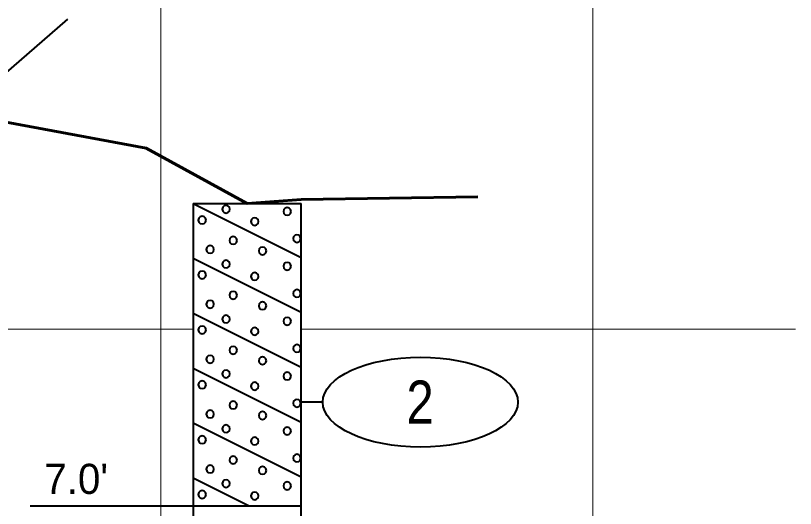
# Model space of a CAD drawing. Extents: x -76 to 974, y -1080 to -735.
# Drawn here: x 190.03 to 208.08, y -936.24 to -924.83 of the extents above; entities that cross this region are included whole.
import ezdxf
from ezdxf.enums import TextEntityAlignment as Align

# ---------------------------------------------------------------- set-up
doc = ezdxf.new("R2010")
doc.units = 0
doc.header["$LTSCALE"] = 0.36
doc.linetypes.add('LONG_DASHED', pattern=[7.5, 6, -1.5])
for name, color, linetype, lineweight in [('27', 7, 'Continuous', 40), ('28', 7, 'LONG_DASHED', 60), ('7', 7, 'Continuous', 13)]:
    doc.layers.add(name, color=color, linetype=linetype, lineweight=lineweight)

msp = doc.modelspace()

# ---------------------------------------------------------------- linework, layer by layer
at = {"layer": '27'}
for p, q in [((188.7243, -927.0998), (191.2447, -924.9175)), ((194.1412, -929.1789), (196.6412, -930.4289)), ((194.1412, -929.1789), (194.1412, -936.1789)), ((194.1412, -929.1789), (196.6412, -929.1789)), ((196.6412, -936.1789), (196.6412, -929.1789)), ((194.1412, -930.4489), (196.6412, -931.6989)), ((194.1412, -931.7189), (196.6412, -932.9689)), ((194.1412, -932.9889), (196.6412, -934.2389)), ((197.1412, -933.7789), (196.6412, -933.7789)), ((194.1412, -934.2589), (196.6412, -935.5089)), ((194.1412, -935.5289), (195.4412, -936.1789)), ((190.3737, -936.1789), (194.1411, -936.1789)), ((194.1412, -936.1789), (196.6412, -936.1789)), ((194.1412, -936.1789), (194.1412, -946.1789)), ((196.6412, -946.1789), (196.6412, -936.1789))]:
    msp.add_line(p, q, dxfattribs=at)
for points in [[(194.9918, -929.3152), (194.9799, -929.2708), (194.9474, -929.2383), (194.9029, -929.2263), (194.8585, -929.2383), (194.826, -929.2708), (194.814, -929.3152), (194.826, -929.3597), (194.8585, -929.3922), (194.9029, -929.4041), (194.9474, -929.3922), (194.9799, -929.3597)], [(196.4067, -929.3662), (196.3948, -929.3217), (196.3622, -929.2892), (196.3178, -929.2773), (196.2733, -929.2892), (196.2408, -929.3217), (196.2289, -929.3662), (196.2408, -929.4106), (196.2733, -929.4432), (196.3178, -929.4551), (196.3622, -929.4432), (196.3948, -929.4106)], [(194.4388, -929.567), (194.4268, -929.5226), (194.3943, -929.49), (194.3499, -929.4781), (194.3054, -929.49), (194.2729, -929.5226), (194.261, -929.567), (194.2729, -929.6115), (194.3054, -929.644), (194.3499, -929.6559), (194.3943, -929.644), (194.4268, -929.6115)], [(195.6541, -929.6001), (195.6422, -929.5556), (195.6096, -929.5231), (195.5652, -929.5112), (195.5207, -929.5231), (195.4882, -929.5556), (195.4763, -929.6001), (195.4882, -929.6445), (195.5207, -929.6771), (195.5652, -929.689), (195.6096, -929.6771), (195.6422, -929.6445)], [(196.633, -929.9942), (196.6211, -929.9497), (196.5885, -929.9172), (196.5441, -929.9053), (196.4996, -929.9172), (196.4671, -929.9497), (196.4552, -929.9942), (196.4671, -930.0386), (196.4996, -930.0712), (196.5441, -930.0831), (196.5885, -930.0712), (196.6211, -930.0386)], [(195.1583, -930.0374), (195.1464, -929.993), (195.1138, -929.9604), (195.0694, -929.9485), (195.0249, -929.9604), (194.9924, -929.993), (194.9805, -930.0374), (194.9924, -930.0819), (195.0249, -930.1144), (195.0694, -930.1263), (195.1138, -930.1144), (195.1464, -930.0819)], [(194.6231, -930.2459), (194.6112, -930.2014), (194.5786, -930.1689), (194.5342, -930.157), (194.4897, -930.1689), (194.4572, -930.2014), (194.4453, -930.2459), (194.4572, -930.2903), (194.4897, -930.3229), (194.5342, -930.3348), (194.5786, -930.3229), (194.6112, -930.2903)], [(195.8359, -930.2789), (195.824, -930.2345), (195.7914, -930.202), (195.747, -930.19), (195.7025, -930.202), (195.67, -930.2345), (195.6581, -930.2789), (195.67, -930.3234), (195.7025, -930.3559), (195.747, -930.3678), (195.7914, -930.3559), (195.824, -930.3234)], [(194.9918, -930.584), (194.9799, -930.5396), (194.9473, -930.5071), (194.9029, -930.4951), (194.8584, -930.5071), (194.8259, -930.5396), (194.814, -930.584), (194.8259, -930.6285), (194.8584, -930.661), (194.9029, -930.6729), (194.9473, -930.661), (194.9799, -930.6285)], [(196.4067, -930.6349), (196.3948, -930.5904), (196.3622, -930.5579), (196.3178, -930.546), (196.2733, -930.5579), (196.2408, -930.5904), (196.2289, -930.6349), (196.2408, -930.6793), (196.2733, -930.7119), (196.3178, -930.7238), (196.3622, -930.7119), (196.3948, -930.6793)], [(194.4388, -930.8358), (194.4268, -930.7913), (194.3943, -930.7588), (194.3499, -930.7469), (194.3054, -930.7588), (194.2729, -930.7913), (194.261, -930.8358), (194.2729, -930.8802), (194.3054, -930.9127), (194.3499, -930.9247), (194.3943, -930.9127), (194.4268, -930.8802)], [(195.6541, -930.8688), (195.6422, -930.8244), (195.6096, -930.7918), (195.5652, -930.7799), (195.5207, -930.7918), (195.4882, -930.8244), (195.4763, -930.8688), (195.4882, -930.9133), (195.5207, -930.9458), (195.5652, -930.9577), (195.6096, -930.9458), (195.6422, -930.9133)], [(196.633, -931.2629), (196.6211, -931.2185), (196.5885, -931.1859), (196.5441, -931.174), (196.4996, -931.1859), (196.4671, -931.2185), (196.4552, -931.2629), (196.4671, -931.3074), (196.4996, -931.3399), (196.5441, -931.3518), (196.5885, -931.3399), (196.6211, -931.3074)], [(195.1583, -931.3061), (195.1464, -931.2617), (195.1138, -931.2291), (195.0694, -931.2172), (195.0249, -931.2291), (194.9924, -931.2617), (194.9805, -931.3061), (194.9924, -931.3506), (195.0249, -931.3831), (195.0694, -931.395), (195.1138, -931.3831), (195.1464, -931.3506)], [(194.6231, -931.5146), (194.6112, -931.4702), (194.5786, -931.4376), (194.5342, -931.4257), (194.4897, -931.4376), (194.4572, -931.4702), (194.4453, -931.5146), (194.4572, -931.5591), (194.4897, -931.5916), (194.5342, -931.6035), (194.5786, -931.5916), (194.6112, -931.5591)], [(195.8359, -931.5477), (195.824, -931.5032), (195.7914, -931.4707), (195.747, -931.4588), (195.7025, -931.4707), (195.67, -931.5032), (195.6581, -931.5477), (195.67, -931.5921), (195.7025, -931.6247), (195.747, -931.6366), (195.7914, -931.6247), (195.824, -931.5921)], [(194.9918, -931.8552), (194.9799, -931.8108), (194.9474, -931.7783), (194.9029, -931.7663), (194.8585, -931.7783), (194.826, -931.8108), (194.814, -931.8552), (194.826, -931.8997), (194.8585, -931.9322), (194.9029, -931.9441), (194.9474, -931.9322), (194.9799, -931.8997)], [(196.4067, -931.9062), (196.3948, -931.8617), (196.3622, -931.8292), (196.3178, -931.8173), (196.2733, -931.8292), (196.2408, -931.8617), (196.2289, -931.9062), (196.2408, -931.9506), (196.2733, -931.9832), (196.3178, -931.9951), (196.3622, -931.9832), (196.3948, -931.9506)], [(194.4388, -932.107), (194.4268, -932.0626), (194.3943, -932.03), (194.3499, -932.0181), (194.3054, -932.03), (194.2729, -932.0626), (194.261, -932.107), (194.2729, -932.1515), (194.3054, -932.184), (194.3499, -932.1959), (194.3943, -932.184), (194.4268, -932.1515)], [(195.6541, -932.1401), (195.6422, -932.0956), (195.6096, -932.0631), (195.5652, -932.0512), (195.5207, -932.0631), (195.4882, -932.0956), (195.4763, -932.1401), (195.4882, -932.1845), (195.5207, -932.2171), (195.5652, -932.229), (195.6096, -932.2171), (195.6422, -932.1845)], [(196.633, -932.5342), (196.6211, -932.4897), (196.5885, -932.4572), (196.5441, -932.4453), (196.4996, -932.4572), (196.4671, -932.4897), (196.4552, -932.5342), (196.4671, -932.5786), (196.4996, -932.6112), (196.5441, -932.6231), (196.5885, -932.6112), (196.6211, -932.5786)], [(195.1583, -932.5774), (195.1464, -932.533), (195.1138, -932.5004), (195.0694, -932.4885), (195.0249, -932.5004), (194.9924, -932.533), (194.9805, -932.5774), (194.9924, -932.6219), (195.0249, -932.6544), (195.0694, -932.6663), (195.1138, -932.6544), (195.1464, -932.6219)], [(194.6231, -932.7859), (194.6112, -932.7414), (194.5786, -932.7089), (194.5342, -932.697), (194.4897, -932.7089), (194.4572, -932.7414), (194.4453, -932.7859), (194.4572, -932.8303), (194.4897, -932.8629), (194.5342, -932.8748), (194.5786, -932.8629), (194.6112, -932.8303)], [(195.8359, -932.8189), (195.824, -932.7745), (195.7914, -932.742), (195.747, -932.73), (195.7025, -932.742), (195.67, -932.7745), (195.6581, -932.8189), (195.67, -932.8634), (195.7025, -932.8959), (195.747, -932.9078), (195.7914, -932.8959), (195.824, -932.8634)], [(194.9918, -933.124), (194.9799, -933.0796), (194.9473, -933.0471), (194.9029, -933.0351), (194.8584, -933.0471), (194.8259, -933.0796), (194.814, -933.124), (194.8259, -933.1685), (194.8584, -933.201), (194.9029, -933.2129), (194.9473, -933.201), (194.9799, -933.1685)], [(196.4067, -933.1749), (196.3948, -933.1304), (196.3622, -933.0979), (196.3178, -933.086), (196.2733, -933.0979), (196.2408, -933.1304), (196.2289, -933.1749), (196.2408, -933.2193), (196.2733, -933.2519), (196.3178, -933.2638), (196.3622, -933.2519), (196.3948, -933.2193)], [(194.4388, -933.3758), (194.4268, -933.3313), (194.3943, -933.2988), (194.3499, -933.2869), (194.3054, -933.2988), (194.2729, -933.3313), (194.261, -933.3758), (194.2729, -933.4202), (194.3054, -933.4527), (194.3499, -933.4647), (194.3943, -933.4527), (194.4268, -933.4202)], [(195.6541, -933.4088), (195.6422, -933.3644), (195.6096, -933.3318), (195.5652, -933.3199), (195.5207, -933.3318), (195.4882, -933.3644), (195.4763, -933.4088), (195.4882, -933.4533), (195.5207, -933.4858), (195.5652, -933.4977), (195.6096, -933.4858), (195.6422, -933.4533)], [(196.633, -933.8029), (196.6211, -933.7585), (196.5885, -933.7259), (196.5441, -933.714), (196.4996, -933.7259), (196.4671, -933.7585), (196.4552, -933.8029), (196.4671, -933.8474), (196.4996, -933.8799), (196.5441, -933.8918), (196.5885, -933.8799), (196.6211, -933.8474)], [(195.1583, -933.8461), (195.1464, -933.8017), (195.1138, -933.7691), (195.0694, -933.7572), (195.0249, -933.7691), (194.9924, -933.8017), (194.9805, -933.8461), (194.9924, -933.8906), (195.0249, -933.9231), (195.0694, -933.935), (195.1138, -933.9231), (195.1464, -933.8906)], [(194.6231, -934.0546), (194.6112, -934.0102), (194.5786, -933.9776), (194.5342, -933.9657), (194.4897, -933.9776), (194.4572, -934.0102), (194.4453, -934.0546), (194.4572, -934.0991), (194.4897, -934.1316), (194.5342, -934.1435), (194.5786, -934.1316), (194.6112, -934.0991)], [(195.8359, -934.0877), (195.824, -934.0432), (195.7914, -934.0107), (195.747, -933.9988), (195.7025, -934.0107), (195.67, -934.0432), (195.6581, -934.0877), (195.67, -934.1321), (195.7025, -934.1647), (195.747, -934.1766), (195.7914, -934.1647), (195.824, -934.1321)], [(194.9918, -934.3952), (194.9799, -934.3508), (194.9474, -934.3183), (194.9029, -934.3063), (194.8585, -934.3183), (194.826, -934.3508), (194.814, -934.3952), (194.826, -934.4397), (194.8585, -934.4722), (194.9029, -934.4841), (194.9474, -934.4722), (194.9799, -934.4397)], [(196.4067, -934.4462), (196.3948, -934.4017), (196.3622, -934.3692), (196.3178, -934.3573), (196.2733, -934.3692), (196.2408, -934.4017), (196.2289, -934.4462), (196.2408, -934.4906), (196.2733, -934.5232), (196.3178, -934.5351), (196.3622, -934.5232), (196.3948, -934.4906)], [(194.4388, -934.647), (194.4268, -934.6026), (194.3943, -934.57), (194.3499, -934.5581), (194.3054, -934.57), (194.2729, -934.6026), (194.261, -934.647), (194.2729, -934.6915), (194.3054, -934.724), (194.3499, -934.7359), (194.3943, -934.724), (194.4268, -934.6915)], [(195.6541, -934.6801), (195.6422, -934.6356), (195.6096, -934.6031), (195.5652, -934.5912), (195.5207, -934.6031), (195.4882, -934.6356), (195.4763, -934.6801), (195.4882, -934.7245), (195.5207, -934.7571), (195.5652, -934.769), (195.6096, -934.7571), (195.6422, -934.7245)], [(195.1583, -935.1174), (195.1464, -935.073), (195.1138, -935.0404), (195.0694, -935.0285), (195.0249, -935.0404), (194.9924, -935.073), (194.9805, -935.1174), (194.9924, -935.1619), (195.0249, -935.1944), (195.0694, -935.2063), (195.1138, -935.1944), (195.1464, -935.1619)], [(196.633, -935.0742), (196.6211, -935.0297), (196.5885, -934.9972), (196.5441, -934.9853), (196.4996, -934.9972), (196.4671, -935.0297), (196.4552, -935.0742), (196.4671, -935.1186), (196.4996, -935.1512), (196.5441, -935.1631), (196.5885, -935.1512), (196.6211, -935.1186)], [(194.6231, -935.3259), (194.6112, -935.2814), (194.5786, -935.2489), (194.5342, -935.237), (194.4897, -935.2489), (194.4572, -935.2814), (194.4453, -935.3259), (194.4572, -935.3703), (194.4897, -935.4029), (194.5342, -935.4148), (194.5786, -935.4029), (194.6112, -935.3703)], [(195.8359, -935.3589), (195.824, -935.3145), (195.7914, -935.282), (195.747, -935.27), (195.7025, -935.282), (195.67, -935.3145), (195.6581, -935.3589), (195.67, -935.4034), (195.7025, -935.4359), (195.747, -935.4478), (195.7914, -935.4359), (195.824, -935.4034)], [(194.9918, -935.664), (194.9799, -935.6196), (194.9473, -935.5871), (194.9029, -935.5751), (194.8584, -935.5871), (194.8259, -935.6196), (194.814, -935.664), (194.8259, -935.7085), (194.8584, -935.741), (194.9029, -935.7529), (194.9473, -935.741), (194.9799, -935.7085)], [(196.4067, -935.7149), (196.3948, -935.6704), (196.3622, -935.6379), (196.3178, -935.626), (196.2733, -935.6379), (196.2408, -935.6704), (196.2289, -935.7149), (196.2408, -935.7593), (196.2733, -935.7919), (196.3178, -935.8038), (196.3622, -935.7919), (196.3948, -935.7593)], [(194.4388, -935.9158), (194.4268, -935.8713), (194.3943, -935.8388), (194.3499, -935.8269), (194.3054, -935.8388), (194.2729, -935.8713), (194.261, -935.9158), (194.2729, -935.9602), (194.3054, -935.9927), (194.3499, -936.0047), (194.3943, -935.9927), (194.4268, -935.9602)], [(195.6541, -935.9488), (195.6422, -935.9044), (195.6096, -935.8718), (195.5652, -935.8599), (195.5207, -935.8718), (195.4882, -935.9044), (195.4763, -935.9488), (195.4882, -935.9933), (195.5207, -936.0258), (195.5652, -936.0377), (195.6096, -936.0258), (195.6422, -935.9933)]]:
    msp.add_lwpolyline(points, close=True, dxfattribs=at)
msp.add_ellipse((199.3986, -933.7789), major_axis=(2.2574, 0), ratio=0.461538, dxfattribs=at)
at = {"layer": '28', "linetype": 'Continuous'}
msp.add_lwpolyline([(132.8909, -930.15), (136.3853, -930.0789), (138.9742, -929.99), (140.3909, -929.92), (145.3909, -930.05), (150.7242, -928.09), (154.3909, -927.86), (154.3909, -928.34), (167.3909, -927.18), (180.7245, -926.63), (183.0579, -926.89), (188.7245, -927.1), (193.0578, -927.9), (195.3912, -929.1789), (196.6412, -929.09), (200.7245, -929.03)], dxfattribs=at)
at = {"layer": '7'}
for p, q in [((193.3912, -1042.0988), (193.3912, -895.7205)), ((203.3912, -1042.0988), (203.3912, -895.7205)), ((138.9742, -932.09), (194.1412, -932.09)), ((196.6412, -932.09), (208.0761, -932.09))]:
    msp.add_line(p, q, dxfattribs=at)

# ---------------------------------------------------------------- texts
at = {"layer": '27', "width": 0.85}
msp.add_text('2', height=1, dxfattribs=at).set_placement((199.3915, -934.2788), align=Align.CENTER)
at = {"layer": '27'}
msp.add_text("7.0'", height=0.6976, dxfattribs=at).set_placement((190.6978, -935.9025))

doc.saveas('drawing.dxf')
